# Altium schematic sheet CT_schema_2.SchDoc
size 316 x 200 mm
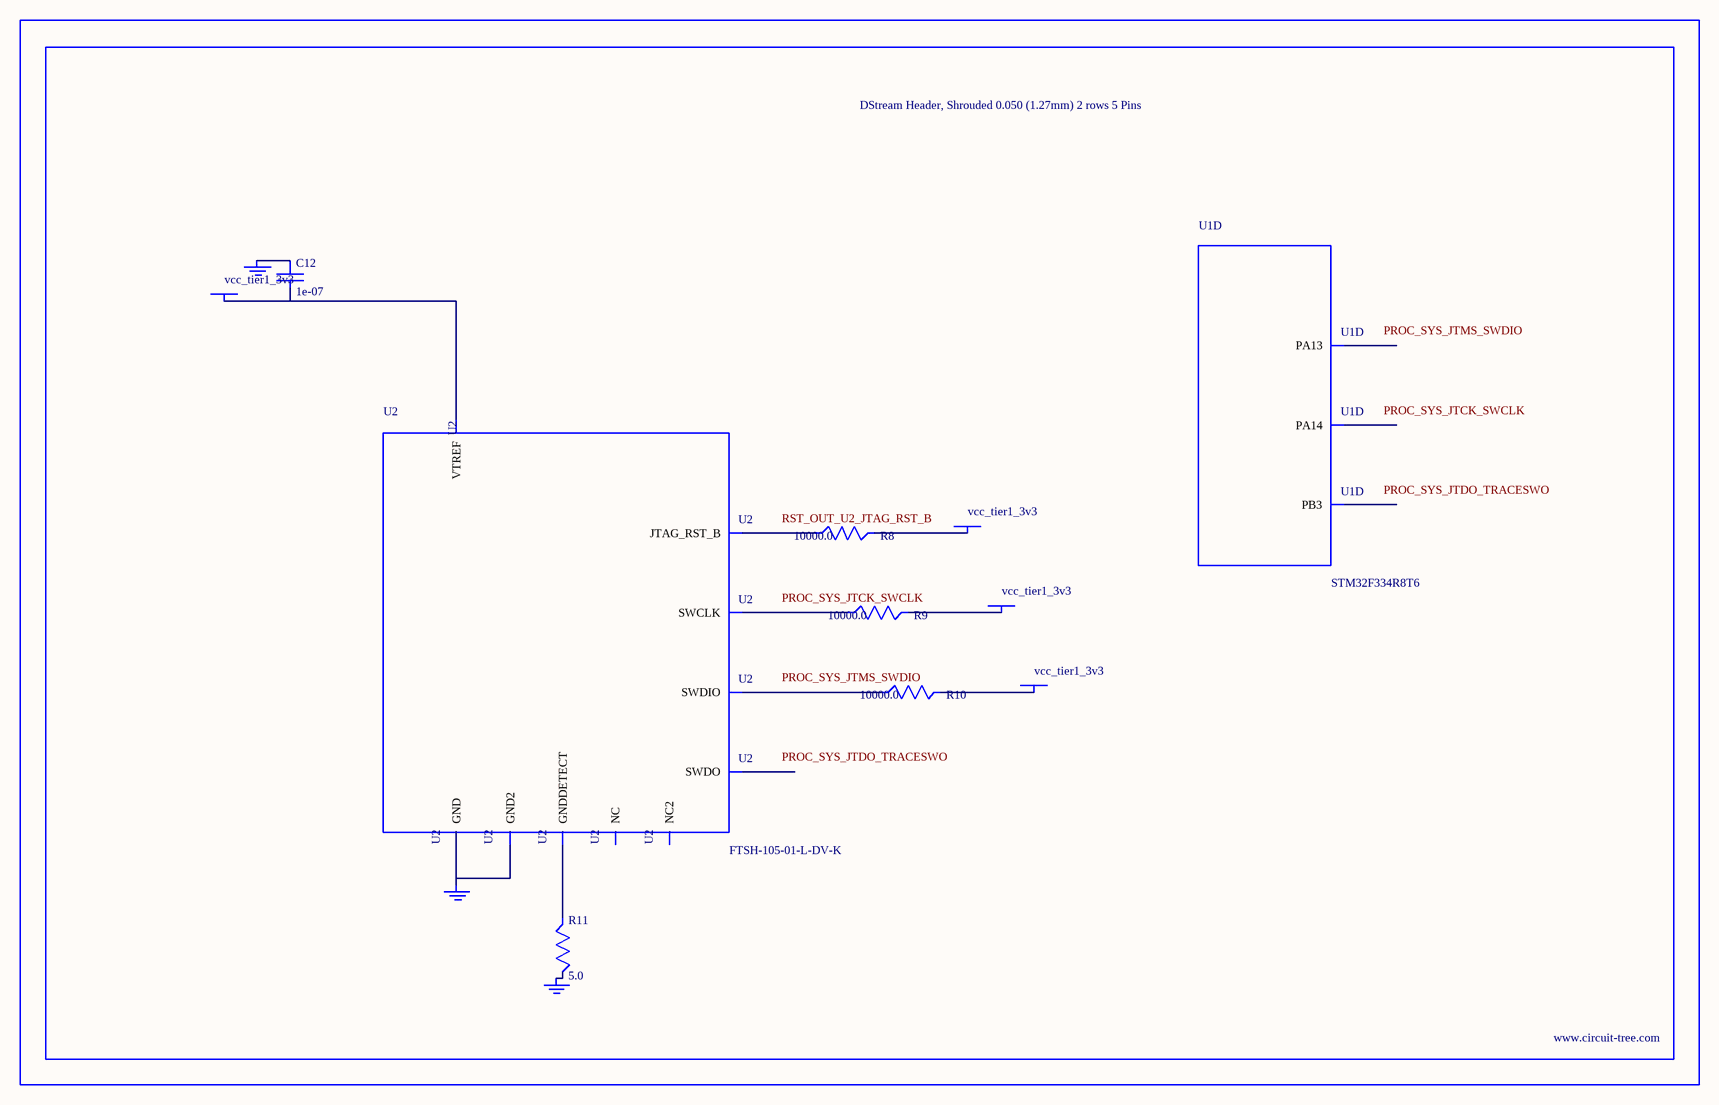
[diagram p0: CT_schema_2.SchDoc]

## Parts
BORDER1  (no value)
C12  1e-07  [C0402]
GND_INSTANCE_1_0  (no value)
GND_INSTANCE_1_1  (no value)
GND_INSTANCE_1_2  (no value)
POWER_INSTANCE_1_0  vcc_tier1_3v3
POWER_INSTANCE_1_1  vcc_tier1_3v3
POWER_INSTANCE_1_2  vcc_tier1_3v3
POWER_INSTANCE_1_3  vcc_tier1_3v3
R8  10000.0  [R0603]
R9  10000.0  [R0603]
R10  10000.0  [R0603]
R11  5.0  [R0603]
U1  STM32F334R8T6  [LQFP64]  (part D of 7)
U2  FTSH-105-01-L-DV-K  [SAMTEC_FTSH-105-01-L-DV-K]

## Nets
NetC12_1: C12.1 GND_INSTANCE_1_0.0(GND)
NetC12_2: C12.2 POWER_INSTANCE_1_0.0(PWR) U2.1(VTREF)
NetGND_INSTANCE_1_1_0: GND_INSTANCE_1_1.0(GND) R11.2
NetGND_INSTANCE_1_2_0: GND_INSTANCE_1_2.0(GND) U2.3(GND) U2.5(GND2)
NetPOWER_INSTANCE_1_1_0: POWER_INSTANCE_1_1.0(PWR) R10.2
NetPOWER_INSTANCE_1_2_0: POWER_INSTANCE_1_2.0(PWR) R9.2
NetPOWER_INSTANCE_1_3_0: POWER_INSTANCE_1_3.0(PWR) R8.2
NetR8_1: R8.1 U2.10(JTAG_RST_B)
NetR9_1: R9.1 U2.4(SWCLK)
NetR10_1: R10.1 U2.2(SWDIO)
NetR11_1: R11.1 U2.9(GNDDETECT)

Not connected (* = marked no-connect by the designer): U1 46(PA13) 49(PA14) 55(PB3); U2 6(SWDO) 7(NC) 8(NC2)

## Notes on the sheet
- Labels drawn without touching a wire or pin: PROC_SYS_JTCK_SWCLK, PROC_SYS_JTDO_TRACESWO, PROC_SYS_JTMS_SWDIO, RST_OUT_U2_JTAG_RST_B

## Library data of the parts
BORDER1 = BORDER_PAGE1
C12 = C0402C104K3RACTU
GND_INSTANCE_1_0-GND_INSTANCE_1_2 = GND
POWER_INSTANCE_1_0-POWER_INSTANCE_1_3 = PWR
R8-R10 = RC0603JR-0710KL
R11 = ERJ-3GEYJ5R1V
